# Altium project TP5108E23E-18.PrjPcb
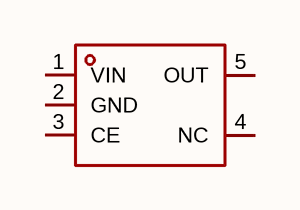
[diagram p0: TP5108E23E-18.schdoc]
1 sheet, 1 parts. Net scope: global (net labels, ports and power ports of the same name join across sheets).

## Sheet TP5108E23E-18.schdoc
size 127 x 101 mm

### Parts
U?  tp5108e23e-18  [SOT-23-5_L3.0-W1.7-P0.95-LS2.8-BL]  (value not drawn)

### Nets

Not connected (* = marked no-connect by the designer): U? 1(VIN) 2(GND) 3(CE) 4(NC) 5(OUT)

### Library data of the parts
U? = tp5108e23e-18: 输出极性:正极;工作电压:7V;输出电压:1.8V;输出电流:500mA;电源纹波抑制比(PSRR):70dB@(1kHz);输出类型:固定;; Manufacturer: TECH PUBLIC(台舟); AddInBom: yes; ModelId: 0a2a1b8f50944f73965918ad6e5fe167; ModelName: SOT-23-5_L2.9-W1.6-H1.1-LS2.8-P0.95; ModelTransform: 118.60433,114.173,0,90,0,0,0.0005,0.0005,0; Output Configuration: 正极; Voltage - Supply: 7V; Output Voltage: 1.8V; Output Current: 500mA; standby current: 80uA; Noise: 50uVrms; Output Type: 固定; Number of Outputs: 1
